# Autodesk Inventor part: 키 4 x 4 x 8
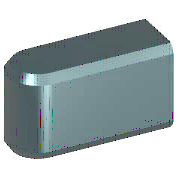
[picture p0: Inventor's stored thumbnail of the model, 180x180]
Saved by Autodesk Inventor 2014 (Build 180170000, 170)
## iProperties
Created: 2012-02
Part Number: 키 4 x 4 x 8
Material: 강철, 연강
Description: 키 및 해당 키홈
Document SubType Name: Modeling
Standard: KS B 1311
Designer: mduedu
Standards Organization: KS
Language: ko-KR
Size Designation: 4 x 4 x 8
Categories: <MemberInstance><Categories><Category DisplayName="샤프트 부품" InternalName="7f7aeb1f-a693-4053-b835-cee3144e0d98" Mnemonic="SHFT"><Category DisplayName="키" Interna
Density: 7.86 g/cm^3
Appearance: 노란색
Mass: 0.94325 g
Surface Area: 1.44138 cm^2
Volume: 0.120006 cm^3
IsCustomPart: 1
Author: mduedu
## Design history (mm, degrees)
sketch "스케치1"
  geometry: L1 (2, 2)-(8, 2); L2 (8, 2)-(8, -2); L3 (8, -2)-(2, -2); L4 (0, 7)-(0, -7) reference; L5 (-5, 0)-(30, 0) reference; A1 r 2 centre (2, 0) between (2, 2) and (2, -2)
  constraints: 6 end point, 3 tangent, 2 point on circle, 1 centre point, 1 horizontal, 1 parallel, 1 perpendicular, 1 point on line
  dimensions: "d0" = 2 radius of A1 (= 0.5 x PB); "d7" = 8 distance between parallel lines of L2 L4 (= NLG)
workplane "Work Plane1"
workplane "Work Plane2"
extrude "본체1" new body sketch "스케치1" taper "d3" = 0 deg; stored distance "d4" = 10
workaxis "Work Axis1"
workplane "Work Plane4"
body "Solid1"
chamfer "모따기1" distance "d8" = 0.25 (= PHH); stored, may be unused: second distance "d9" = 0.25 (= PHH), angle "d13" = 45 deg
other parameters: "d1" = -2.5 (= -PNT), "d2" = 1.5 (= PH - PNT), "NLG" = 8 [user parameter; used in 2 equation terms], "PB" = 4 [user parameter; used in 1 equation term], "PNT" = 2.5 [user parameter; used in 2 equation terms], "PH" = 4 [user parameter; used in 1 equation term], "PHH" = 0.25 [user parameter; used in 2 equation terms], "d10" = 0, "d16" = 0, "d17" = 0, "d18" = 0, "RR" = 0.08 [user parameter], "WDMAX" = 12 [user parameter], "PLB1" = 8 (= NLG) [user parameter], "PUEB" = 1.8 [user parameter]
